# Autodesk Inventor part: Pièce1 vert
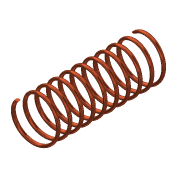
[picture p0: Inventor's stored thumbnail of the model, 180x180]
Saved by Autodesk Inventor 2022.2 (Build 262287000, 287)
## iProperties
Created: 2016-09
Part Number: Pièce1 vert
Material: Rame
Document SubType Name: Modeling
Designer: 18907419
Density: 8.94 g/cm^3
Appearance: Rame - Satinato
Author: 18907419
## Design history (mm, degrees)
feature "Solido1"
node "Solido2"
